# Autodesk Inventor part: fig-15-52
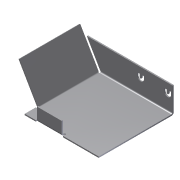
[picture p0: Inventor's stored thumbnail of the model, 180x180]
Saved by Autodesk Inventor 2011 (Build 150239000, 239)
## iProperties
Shininess: 77.0
Angle Display Precision: 2
Document Length Units: 11269
Document Angle Units: 11279
Document Time Units: 11290
Document Mass Units: 11283
Document Length Units Precision: 3
Document Angle Units Precision: 2
Created: 2002-04
Part Number: fig-15-52
Document SubType Name: Sheet Metal
Density: 1 g/cm^3
Sheet Metal Rule: Default
Density: 0.0
Volumn: 0.0
Area: 0.0
PropertySet Name: Model Information
Control State: 0
Master: False
Checked Out: False
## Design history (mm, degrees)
node "Face1"
  sketch "Sketch1"
    geometry: L1 (12.647, 25.882)-(12.647, -14.118); L2 (12.647, -14.118)-(-17.353, -14.118); L3 (-17.353, -14.118)-(-17.353, 15.882); L4 (-17.353, 15.882)-(-2.353, 15.882); L5 (-2.353, 15.882)-(-2.353, 25.882); L6 (-2.353, 25.882)-(12.647, 25.882); 1 further point
    constraints: 12 end point, 4 parallel, 1 perpendicular
    dimensions: "d5" = 30 distance of L2.end L3.end; "d6" = 10 distance of L4.end L5.end; "d7" = 15 distance of L3.end L4.end; "d25" = 15 distance of L5.end L1.start
sketch "Sketch3"
  geometry: L1 (10, -15)-(10, 0)
  constraints: 2 end point
feature "Fold3" sketch "Sketch3" dims "d26" = 0.5 (= BendRadius), "d27" = 90 deg, "d28" = 0.5 (= BendRadius), "d96" = 0.5 (= BendReliefWidth), "d97" = 0.25 (= BendReliefDepth), "d98" = 1 (= MinimumRemnant), "SeamGap" = 0.01, "Thickness" = 0.5
node "Flange2"
sketch "Sketch6"
  geometry: L1 (-6.914, 3.413)-(-5.843, 3.413); L2 (-5.843, 0.624)-(-6.914, 0.624); L3 (-6.914, 2.432)-(-5.843, 2.432); L4 (-5.843, 1.605)-(-6.914, 1.605); L5 (-6.914, 0.624)-(-6.914, 1.605); L6 (-6.914, 2.432)-(-6.914, 3.413); L7 (-6.914, 12.568)-(-6.914, 11.587); L8 (-6.914, 14.376)-(-6.914, 13.395); L9 (-6.914, 11.587)-(-5.843, 11.587); L10 (-5.843, 14.376)-(-6.914, 14.376); L11 (-6.914, 12.568)-(-5.843, 12.568); L12 (-5.843, 13.395)-(-6.914, 13.395); A1 r 1.394 centre (-5.843, 2.018) between (-5.843, 0.624) and (-5.843, 3.413); A2 r 0.413 centre (-5.843, 2.018) between (-5.843, 1.605) and (-5.843, 2.432); A3 r 1.394 centre (-5.843, 12.982) between (-5.843, 11.587) and (-5.843, 14.376); A4 r 0.413 centre (-5.843, 12.982) between (-5.843, 12.568) and (-5.843, 13.395)
  constraints: 24 end point, 8 point on circle, 4 centre point, 3 equal length, 1 perpendicular
cut "Cut1" sketch "Sketch6" dims "d49" = 0.5 (= Thickness), "d50" = 0
node "Flange3"
feature "Corner3" dims "d107" = 2 (= CornerReliefSize), "d108" = 0.5 (= BendRadius), "d109" = 0.5 (= GapSize), "d110" = 0, "d111" = 10, "Thickness" = 0.5
body "Solid1"
face "Plate1" dims "Thickness" = 0.5
sketch "Sketch5"
  geometry: L1 (20, 0)-(5, 0); L2 (5, 0)-(5, 15); L3 (5, 15)-(20, 15); L4 (20, 15)-(20, 0)
  constraints: 8 end point
face "Plate6" dims "d35" = 10, "d36" = 5, "d38" = 15, "d39" = 60 deg, "d40" = 0.5 (= BendRadius), "Thickness" = 0.5, "MinimumRemnant" = 1 (= 2 x Thickness), "BendReliefWidth" = 0.5 (= Thickness)
bend "Bend5" dims "d38" = 15, "d39" = 60 deg, "d40" = 0.5 (= BendRadius), "d99" = 0.5 (= BendReliefWidth), "d100" = 0.25 (= BendReliefDepth), "d101" = 1 (= MinimumRemnant), "SeamGap" = 0.01, "Thickness" = 0.5, "MinimumRemnant" = 1 (= 2 x Thickness), "BendReliefWidth" = 0.5 (= Thickness), "TransitionRadius" = 0.5 (= BendRadius)
sketch "Sketch7"
  geometry: L1 (25, 0)-(15, 0); L2 (15, 0)-(15, 5); L3 (15, 5)-(25, 5); L4 (25, 5)-(25, 0)
  constraints: 8 end point
face "Plate7" dims "d57" = 5, "d58" = 10, "d60" = 5, "d61" = 90 deg, "d62" = 0.5 (= BendRadius), "Thickness" = 0.5, "MinimumRemnant" = 1 (= 2 x Thickness), "BendReliefWidth" = 0.5 (= Thickness)
bend "Bend7" dims "d59" = 0.5 (= BendRadius), "d60" = 5, "d61" = 90 deg, "d62" = 0.5 (= BendRadius), "d102" = 0.5 (= BendReliefWidth), "d103" = 0.25 (= BendReliefDepth), "d104" = 1 (= MinimumRemnant), "SeamGap" = 0.01, "Thickness" = 0.5, "MinimumRemnant" = 1 (= 2 x Thickness), "BendReliefWidth" = 0.5 (= Thickness)
other parameters: "BendRadius" = 0.5 (= Thickness), "BendReliefDepth" = 0.25 (= 0.5 x Thickness), "CornerReliefSize" = 2 (= 4 x Thickness), "d0" = 0.5 (= BendRadius), "d13" = 0.5 (= BendRadius), "d31" = 0.5 (= BendRadius), "d37" = 0.5 (= BendRadius), "JacobiRadiusSize" = 0.5 (= Thickness), "GapSize" = 0.5 (= Thickness)
